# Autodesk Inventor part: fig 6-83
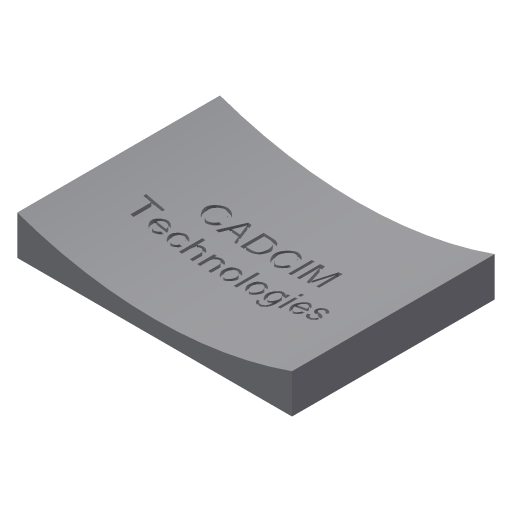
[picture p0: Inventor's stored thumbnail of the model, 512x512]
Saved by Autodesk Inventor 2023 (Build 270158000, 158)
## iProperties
Part Number: fig 6-83
Document SubType Name: Modeling
Created: 2002-12
Designer: deepak
Density: 1 g/cm^3
Material: Generic
Appearance: Default
Control State: 0
Master: False
Checked Out: False
Shininess: 64.0
Length Units: 11269
Angle Units: 11279
Time Units: 11290
Mass Units: 11283
Length Display Precision: 3
Angle Display Precision: 2
Compacted: True
Density: 0.0
Volumn: 0.0
Area: 0.0
PropertySet Name: Model Information
Author: deepak
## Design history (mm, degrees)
sketch "Sketch1"
  geometry: L1 (-39.922, 33.786)-(30.103, 33.786); L2 (30.103, 33.786)-(30.103, -17.894); L3 (30.103, -17.894)-(-39.922, -17.894); L4 (-39.922, -17.894)-(-39.922, 33.786)
  constraints: 8 end point, 2 parallel, 1 horizontal, 1 perpendicular
extrude "Extrusion1" new body sketch "Sketch1" distance "d0" = 10; taper "d1" = 0 deg
workplane "Work Plane1"
sketch "Sketch2"
  geometry: L1 (-37.656, 15.034)-(26.28, 15.034); L2 (26.28, 15.034)-(26.28, 10.168); L3 (26.28, 10.168)-(-37.656, 10.168); L4 (-37.656, 10.168)-(-37.656, 15.034)
  constraints: 2 other
sketch "Sketch3"
  geometry: L1 (70.026, 10)-(0, 10) reference; A1 r 105 centre (35.013, 108.99) between (0, 10) and (70.026, 10)
  constraints: 2 point on circle, 1 centre point
  dimensions: "d5" = 105 radius of A1
extrude "Extrusion2" cut sketch "Sketch3" extent not by distance; stored distance "d3" = 10; taper "d4" = 0 deg
emboss "Emboss4" sketch "Sketch2" dims "d14" = 1, "d15" = 0
body "Solid1"
other parameters: "d2" = 5
